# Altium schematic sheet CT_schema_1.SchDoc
size 451 x 258 mm
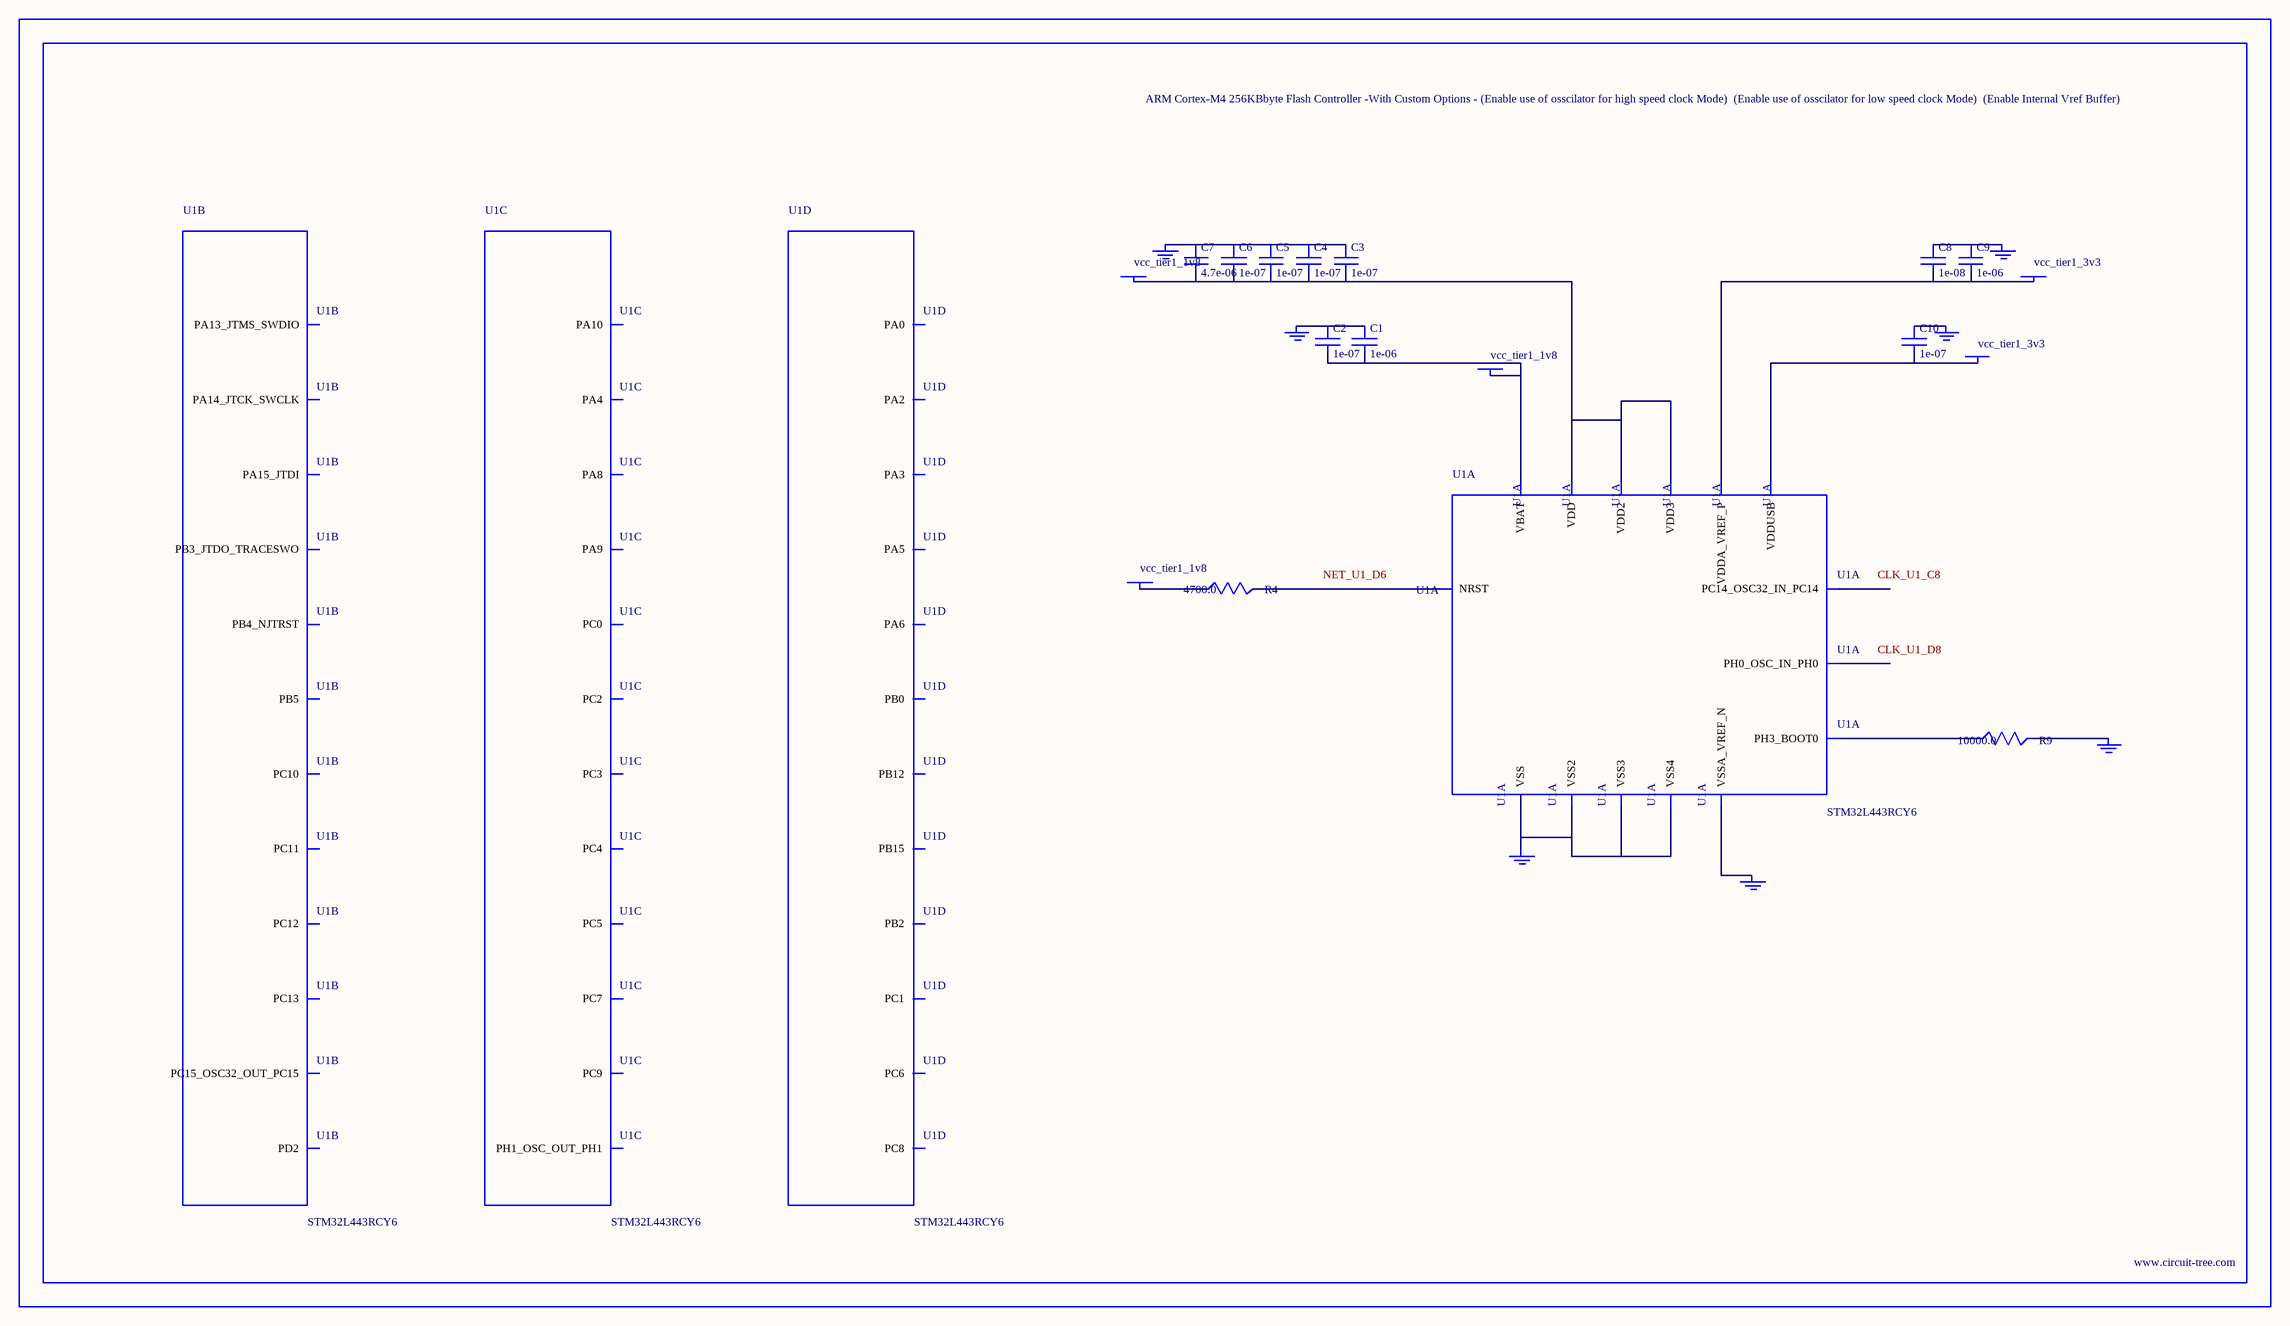
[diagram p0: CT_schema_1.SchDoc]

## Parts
BORDER0  (no value)
C1  1e-06  [C0603]
C2  1e-07  [C0603]
C3  1e-07  [C0603]
C4  1e-07  [C0603]
C5  1e-07  [C0603]
C6  1e-07  [C0603]
C7  4.7e-06  [C0603]
C8  1e-08  [C0603]
C9  1e-06  [C0603]
C10  1e-07  [C0603]
GND_INSTANCE_0_0  (no value)
GND_INSTANCE_0_1  (no value)
GND_INSTANCE_0_2  (no value)
GND_INSTANCE_0_3  (no value)
GND_INSTANCE_0_4  (no value)
GND_INSTANCE_0_5  (no value)
GND_INSTANCE_0_6  (no value)
POWER_INSTANCE_0_0  vcc_tier1_1v8
POWER_INSTANCE_0_1  vcc_tier1_1v8
POWER_INSTANCE_0_2  vcc_tier1_3v3
POWER_INSTANCE_0_3  vcc_tier1_3v3
POWER_INSTANCE_0_4  vcc_tier1_1v8
R4  4700.0  [R0603]
R9  10000.0  [R0603]
U1  STM32L443RCY6  [WLCSP64]  (parts A,B,C,D of 7)

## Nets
NetC1_1: C1.1 C2.1 GND_INSTANCE_0_0.0(GND)
NetC1_2: C1.2 C2.2 POWER_INSTANCE_0_0.0(PWR) U1.B7(VBAT)
NetC3_1: C3.1 C4.1 C5.1 C6.1 C7.1 GND_INSTANCE_0_1.0(GND)
NetC3_2: C3.2 C4.2 C5.2 C6.2 C7.2 POWER_INSTANCE_0_1.0(PWR) U1.A8(VDD) U1.H1(VDD2) U1.H7(VDD3)
NetC8_1: C8.1 C9.1 GND_INSTANCE_0_3.0(GND)
NetC8_2: C8.2 C9.2 POWER_INSTANCE_0_2.0(PWR) U1.G8(VDDA_VREF_P)
NetC10_1: C10.1 GND_INSTANCE_0_4.0(GND)
NetC10_2: C10.2 POWER_INSTANCE_0_3.0(PWR) U1.A1(VDDUSB)
NetGND_INSTANCE_0_2_0: GND_INSTANCE_0_2.0(GND) R9.2
NetGND_INSTANCE_0_5_0: GND_INSTANCE_0_5.0(GND) U1.F8(VSSA_VREF_N)
NetGND_INSTANCE_0_6_0: GND_INSTANCE_0_6.0(GND) U1.A7(VSS) U1.B1(VSS2) U1.H2(VSS3) U1.H8(VSS4)
NetPOWER_INSTANCE_0_4_0: POWER_INSTANCE_0_4.0(PWR) R4.1
NetR4_2: R4.2 U1.D6(NRST)
NetR9_1: R9.1 U1.C5(PH3_BOOT0)

Not connected (* = marked no-connect by the designer): U1 A2(PA15_JTDI) A3(PC12) A4(PD2) A5(PB3_JTDO_TRACESWO) B2(PA14_JTCK_SWCLK) B3(PC11) B4(PB4_NJTRST) B8(PC13) C2(PA13_JTMS_SWDIO) C3(PC10) C4(PB5) C7(PC15_OSC32_OUT_PC15) C8(PC14_OSC32_IN_PC14) D1(PA9) D2(PA10) D4(PC4) D5(PC0) D7(PH1_OSC_OUT_PH1) D8(PH0_OSC_IN_PH0) E1(PC7) E2(PC9) E3(PA8) E4(PC5) E5(PA4) E6(PC3) E7(PC2) E8(PC1) F1(PC6) F2(PB15) F3(PC8) F4(PB0) F5(PA5) F6(PA2) F7(PA0) G3(PB12) G4(PB2) G5(PA6) G6(PA3)

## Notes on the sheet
- Labels drawn without touching a wire or pin: CLK_U1_C8, CLK_U1_D8, NET_U1_D6

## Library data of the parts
BORDER0 = BORDER_PAGE0
C1 C9 = C0603C105K3RACTU
C2-C6 C10 = 06035C104K4Z2A
C7 = GRM188R6YA475KE15D
C8 = 06035C103K4Z2A
GND_INSTANCE_0_0-GND_INSTANCE_0_6 = GND
POWER_INSTANCE_0_0-POWER_INSTANCE_0_4 = PWR
R4 = RC0603JR-074K7L
R9 = RC0603JR-0710KL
